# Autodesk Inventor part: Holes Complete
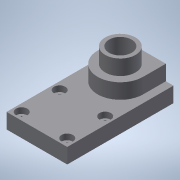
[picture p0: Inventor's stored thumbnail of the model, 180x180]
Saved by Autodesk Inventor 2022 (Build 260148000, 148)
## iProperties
Created: 2013-12
Part Number: Holes Complete
Material: Generic
Document SubType Name: Modeling
Designer: John
Density: 1 g/cm^3
Appearance: Default
Author: John
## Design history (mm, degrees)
sketch "Sketch1"
  geometry: L1 (0, 0)-(-50.8, 0); L2 (-50.8, 0)-(-50.8, -88.9); L3 (-50.8, -88.9)-(0, -88.9); L4 (0, -88.9)-(0, 0)
  constraints: 8 end point, 2 parallel, 1 horizontal, 1 perpendicular
  dimensions: "d0" = 50.8 distance of L3.end L2.end; "d1" = 88.9 distance of L2.end L1.end
extrude "Extrusion1" new body sketch "Sketch1" distance "d2" = 12.7; taper "d3" = 0 deg
sketch "Sketch2"
  geometry: L1 (50.8, 0)-(50.8, 88.9) reference; L2 (50.8, 88.9)-(0, 88.9) reference; L3 (0, 88.9)-(0, 0) reference; L4 (6.35, 88.9)-(44.45, 88.9); L5 (44.45, 88.9)-(44.45, 69.85); L6 (44.45, 69.85)-(6.35, 69.85); L7 (6.35, 69.85)-(6.35, 88.9); L8 (6.35, 79.375)-(0, 79.375); L9 (44.45, 79.375)-(50.8, 79.375); 1 further point
  constraints: 12 end point, 3 midpoint, 3 perpendicular, 3 point on line, 2 parallel, 1 collinear, 1 horizontal, 1 horizontal alignment, 2 other
  dimensions: "d4" = 19.05 distance of L4.end L5.end; "d5" = 6.35 distance between parallel lines of L3 L7
extrude "Extrusion2" join sketch "Sketch2" distance "d6" = 12.7; taper "d7" = 0 deg
sketch "Sketch3"
  geometry: C1 r 12.7 at (25.4, 69.85); A1 r 19.05 centre (25.4, 69.85) between (6.35, 69.85) and (44.45, 69.85) reference; 1 further point
  constraints: 1 centre point, 1 coincident
  dimensions: "d8" = 25.4 diameter of C1
extrude "Extrusion3" join sketch "Sketch3" distance "d9" = 12.7; taper "d10" = 0 deg
sketch "Sketch6"
  geometry: L1 (0, 88.9)-(0, 0) reference; L2 (0, 0)-(50.8, 0) reference; L3 (50.8, 0)-(50.8, 88.9) reference; L4 (44.45, 88.9)-(44.45, 6.35); L5 (44.45, 6.35)-(6.35, 6.35); L6 (6.35, 6.35)-(6.35, 88.9); L7 (6.35, 38.1)-(44.45, 38.1)
  constraints: 8 end point, 2 point on line, 1 perpendicular, 2 other
  dimensions: "d35" = 6.35 distance between parallel lines of L2 L5; "d36" = 31.75 distance between parallel lines of L5 L7
hole "Hole3" diameter "d39" = 19.05; stored, may be unused: countersink angle "d43" = 82 deg, drill point angle "d45" = 118 deg; dims "d37" = 25.4, "d38" = 25.4, "d40" = 19.05, "d41" = 9.525, "d42" = 6.35, "d44" = 25.4
sketch "Sketch7"
  geometry: L1 (0, 0)-(0, 12.7) reference; L2 (44.45, 12.7)-(6.35, 12.7); 1 further point
  constraints: 2 end point, 1 midpoint, 1 perpendicular
hole "Hole4" sketch "Sketch7" at (25.4, 12.7) diameter "d46" = 4.9784; stored, may be unused: countersink angle "d50" = 82 deg, drill point angle "d52" = 118 deg; dims "d47" = 19.05, "d48" = 9.525, "d49" = 6.35, "d51" = 25.4
hole "Hole5" sketch "Sketch6" diameter "d53" = 5.1054; stored, may be unused: countersink angle "d57" = 82 deg, drill point angle "d59" = 118 deg; dims "d54" = 19.05, "d55" = 9.525, "d56" = 4.826, "d58" = 25.4
body "Solid1"
